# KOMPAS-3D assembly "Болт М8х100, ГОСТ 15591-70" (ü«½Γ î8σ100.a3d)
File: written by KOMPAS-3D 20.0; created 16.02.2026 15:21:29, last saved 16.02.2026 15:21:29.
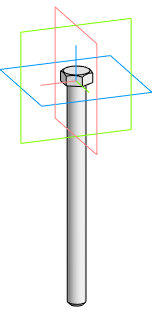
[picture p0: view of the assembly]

Document properties: Автор: admin; Полное имя файла: P:\INSTART\Технический отдел\ОР\Прочие задачи\КД на номенклатурный ряд\КД на типоразмеры дросселей\Сетевые дроссели ISF\ISF-4\Тип 1\ISF-132_256-4\0723\Новая папка\Болт М8х100.a3d

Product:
- Part/product: Болт М8х100  | designation ГОСТ 15591-70
  - Component [detail]: Болт М8x100 ГОСТ 15591-70  | source file: Болт М8x100 ГОСТ 15591-70.m3d

Referenced files in P:\INSTART\Технический отдел\ОР\Прочие задачи\КД на номенклатурный ряд\КД на типоразмеры дросселей\Сетевые дроссели ISF\ISF-4\Тип 1\ISF-132_256-4\0723\Новая папка\: Болт М8x100 ГОСТ 15591-70.m3d
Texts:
  ГОСТ 15591-70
